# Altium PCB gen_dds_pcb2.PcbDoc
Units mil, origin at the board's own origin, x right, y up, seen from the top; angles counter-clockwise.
Board outline 6000 x 4000 mil, 2 copper layers (Top Layer, Bottom Layer); 89 components, 66 nets, 298 pads, 57 vias.
Unrouted connection lines stored in the file: 1.
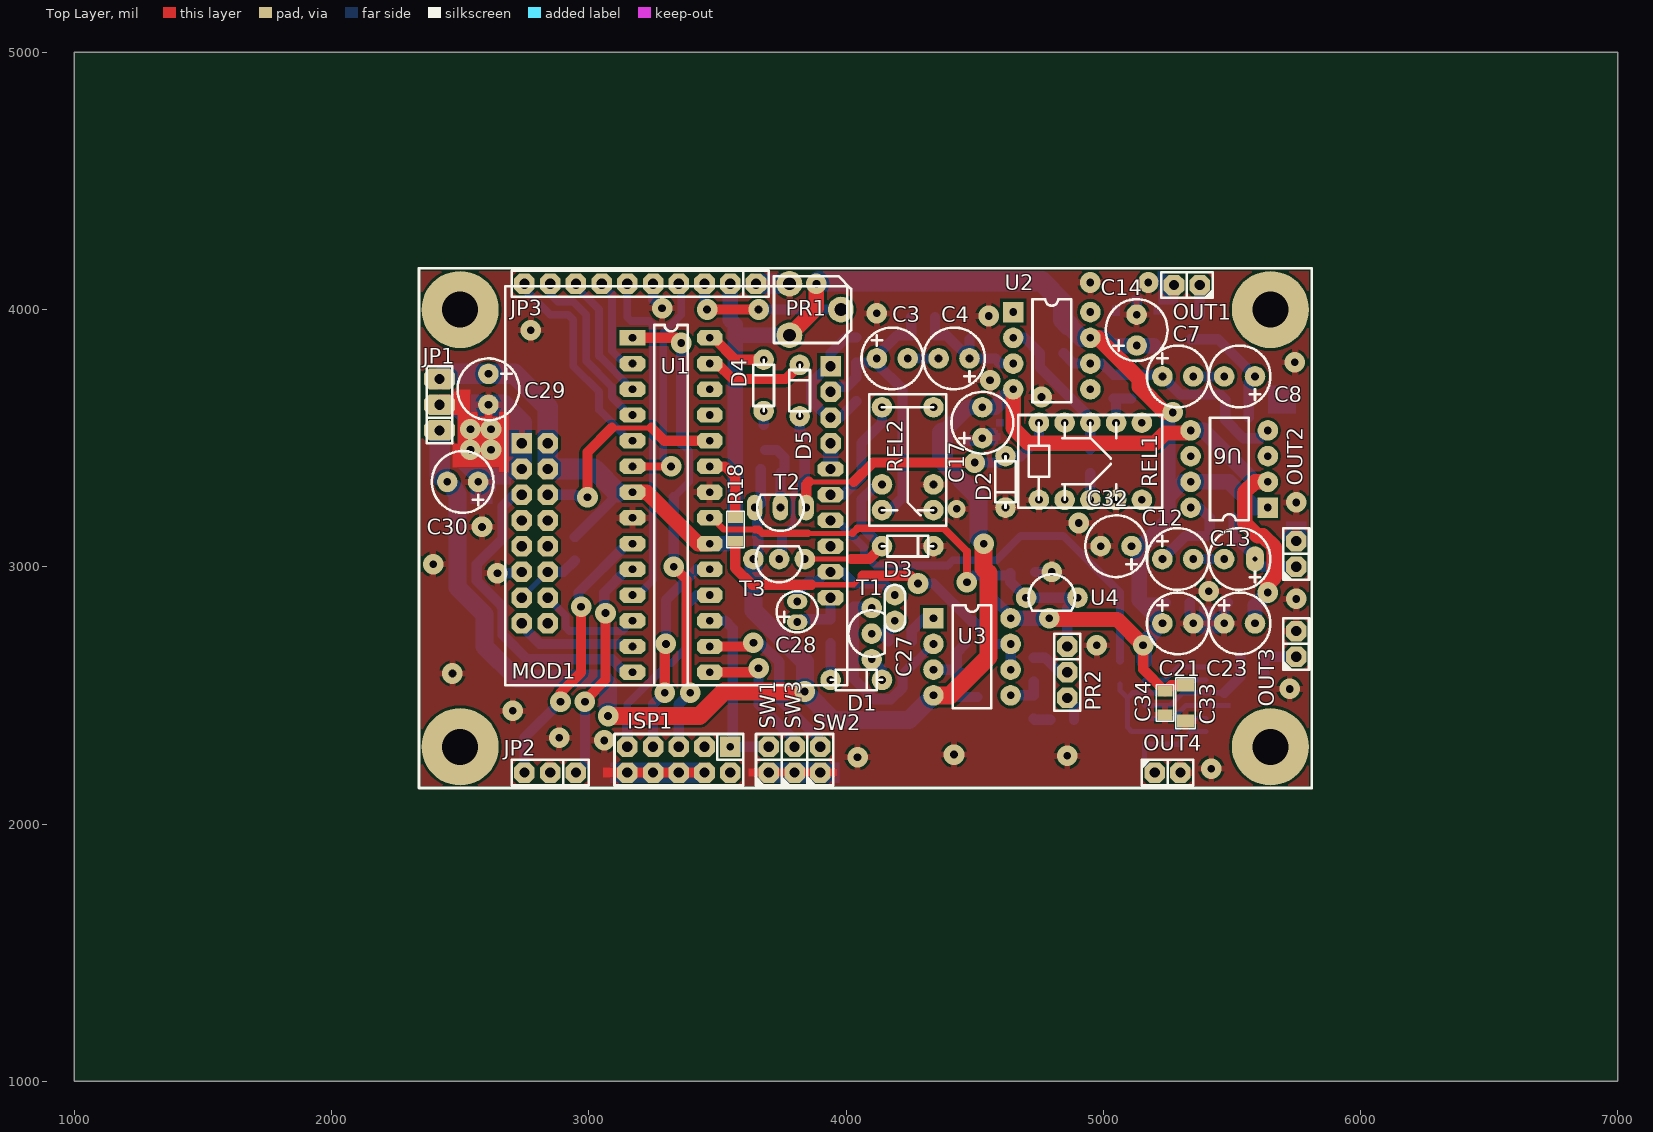
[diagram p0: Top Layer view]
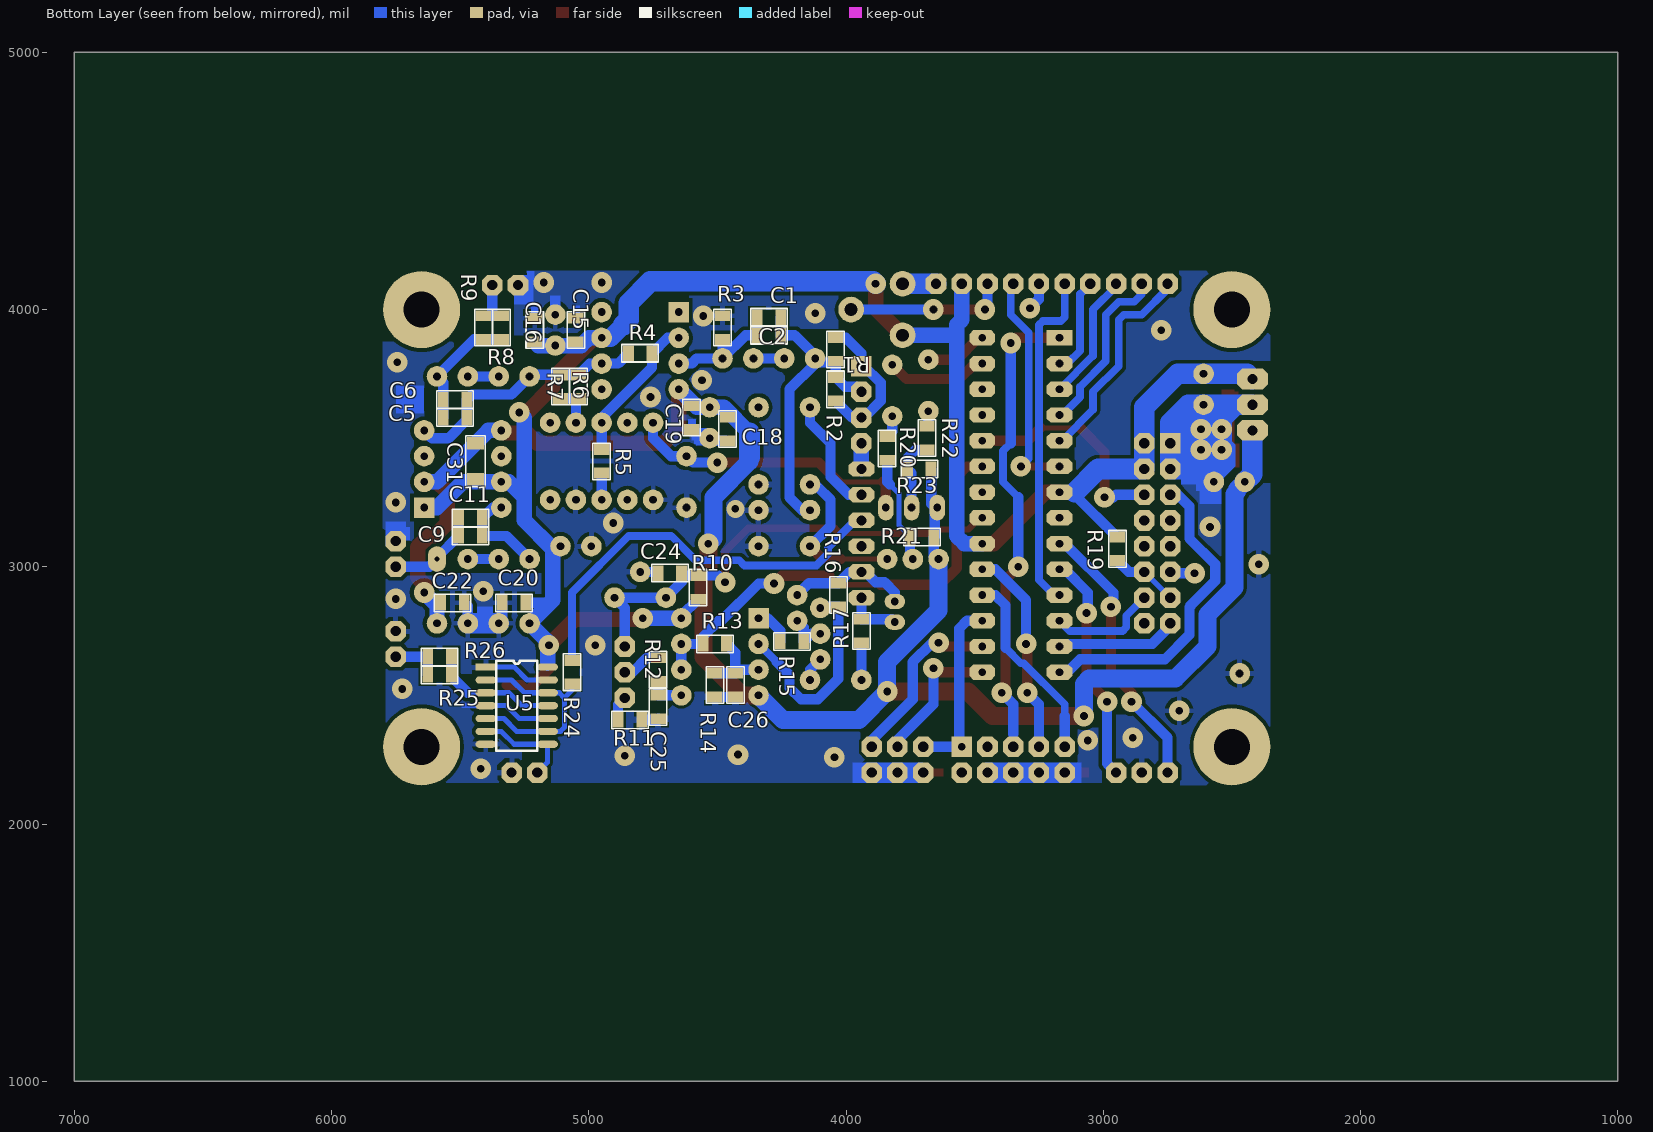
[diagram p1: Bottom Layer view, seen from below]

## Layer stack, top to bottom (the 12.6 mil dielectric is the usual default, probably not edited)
Top Layer: signal copper 1.4
Dielectric: dielectric 12.6, FR-4, Dk 4.8
Bottom Layer: signal copper 1.4

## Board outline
1000,1000 7000,1000 7000,5000 1000,5000

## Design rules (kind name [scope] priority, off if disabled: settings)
Clearance [All] p1: gap=11
PlaneConnect [All] p1: planeconnectstyle=Relief reliefexpansion=20 reliefentries=4 reliefconductorwidth=20 reliefairgap=10
PolygonConnect [All] p1: connectstyle=Relief reliefconductorwidth=25 reliefentries=4 polygonreliefangle="90 Angle"
RoutingVias [All] p1: holewidth=20 width=80 viastyle="Through Hole" minholewidth=20 minwidth=70 maxholewidth=20 maxwidth=80
SilkscreenOverComponentPads [All] p1: minsilkscreentomaskgap=10
SolderMaskExpansion [All] p1: expansion=4
Width [All] p1: maxlimit=120 minlimit=10 preferedwidth=10 minimp=50.000000 maximp=50.000000 favimp=50.000000
26 further rules are at their usual default settings.

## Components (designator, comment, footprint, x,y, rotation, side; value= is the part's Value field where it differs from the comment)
C1 "100n" 0805 4300,3970 r0 bottom
C2 "1n" 0805 4300,3900 r0 bottom
C3 "220u" CE6#1 4180,3810 r0 top
C4 "220u" CE6#1 4420,3810 r180 top
C5 "100n" 0805 5520,3580 r0 bottom
C6 "1n" 0805 5520,3650 r0 bottom
C7 "220u" CE6#1 5290,3740 r0 top
C8 "220u" CE6#1 5530,3740 r180 top
C9 "1n" 0805 5460,3120 r0 bottom
C11 "100n" 0805 5460,3190 r0 bottom
C12 "220u" CE6#1 5290,3030 r0 top
C13 "220u" CE6#2 5530,3030 r180 top
C14 "100u" CE6#1 5130,3920 r90 top
C15 "100n" 0805 5050,3920 r90 bottom
C16 "1n" 0805 5210,3920 r90 bottom
C17 "100u" CE6#1 4530,3560 r90 top
C18 "100n" 0805 4460,3535 r270 bottom
C19 "1n" 0805 4600,3580 r270 bottom
C20 "100n" 0805 5290,2860 r0 bottom
C21 "100u" CE6#1 5290,2780 r0 top
C22 "100n" 0805 5530,2860 r180 bottom
C23 "100u" CE6#1 5530,2780 r0 top
C24 "100n" 0805 4685,2975 r0 bottom
C25 "100n" 0805 4730,2455 r270 bottom
C26 "100n" 0805 4430,2540 r270 bottom
C27 "1u" C100 4190,2790 r90 top
C28 "10u" CE4 3810,2825 r90 top
C29 "220u" CE6#1 2610,3690 r270 top
C30 "220u" CE6#1 2510,3330 r180 top
C31 "1u" 1206 5440,3410 r90 bottom
C32 "100u" CE6#1 5050,3080 r180 top
C33 "1u" 1206 5320,2470 r270 top
C34 "1n" 0805 5240,2470 r270 top
D1 "BAT46" DO-35/200 3940,2560 r0 top
D2 "1N4148" DO-35/200 4620,3430 r270 top
D3 "1N4148" DO-35/200 4140,3080 r0 top
D4 "7V5" DO-35/200 3680,3605 r90 top
D5 "7V5" DO-35/200 3820,3585 r90 top
ISP1 "ISP" G2*5 3550,2300 r270 top
JP1 "ZASILANIE" G3#1 2420,3530 r180 top
JP2 "IMPULSATOR" G3#2 2950,2200 r270 top
JP3 "LCD2*16" G10 3650,4100 r270 top
MOD1 "DDS_MODUL" DDS_MODUL 2740,3480 r90 top
OUT1 "BNC" G2 5375,4095 r270 top
OUT2 "BNC" G2 5750,3000 r180 top
OUT3 "BNC" G2 5750,2650 r180 top
OUT4 "BNC" G2 5200,2200 r90 top
PR1 "10k" RM065 3880,4000 r180 top
PR2 "4,7k" G3#2 4860,2690 r0 top
R1 "100" 0805 4040,3845 r270 bottom
R2 "100" 0805 4040,3690 r270 bottom
R3 "4,7k" 0805 4480,3930 r270 bottom
R4 "510" 0805 4800,3830 r0 bottom
R5 "20" 0805 4950,3410 r90 bottom
R6 "470" 0805 5040,3700 r90 bottom
R7 "680" 0805 5110,3700 r90 bottom
R8 "100" 0805 5340,3930 r90 bottom
R9 "100" 0805 5410,3930 r90 bottom
R10 "1k" 0805 4575,2920 r270 bottom
R11 "100" 0805 4840,2405 r0 bottom
R12 "10k" 0805 4730,2600 r270 bottom
R13 "12k" 0805 4510,2700 r180 bottom
R14 "3k" 0805 4510,2540 r90 bottom
R15 "1k" 0805 4210,2710 r180 bottom
R16 "820" 0805 4030,2890 r270 bottom
R17 "100" 0805 3940,2750 r90 bottom
R18 "1k" 0805 3570,3145 r270 top
R19 "10k" 0805 2945,3070 r90 bottom
R20 "1k" 0805 3840,3460 r270 bottom
R21 "100k" 0805 3705,3115 r0 bottom
R22 "1k" 0805 3685,3500 r90 bottom
R23 "100k" 0805 3715,3380 r0 bottom
R24 "100" 0805 5065,2590 r270 bottom
R25 "100" 0805 5580,2580 r0 bottom
R26 "100" 0805 5580,2650 r0 bottom
REL1 "AZ850-5" AZ850 4950,3410 r90 top
REL2 "HFD23 005-1ZS" JRC23 4240,3620 r0 top
SW1 "SWITCH" G2 3700,2200 r180 top
SW2 "SWITCH" G2 3900,2200 r180 top
SW3 "SWITCH" G2 3800,2200 r180 top
T1 "BC547" TO92 4100,2640 r180 top
T2 "BC547" TO92A 3845,3230 r270 top
T3 "BC547" TO92 3840,3030 r270 top
U1 "ATMEGA8" DIP28A 3170,3890 r0 top
U2 "HFA1100" DIP8 4650,3990 r0 top
U3 "LM358" DIP8 4340,2800 r0 top
U4 "TL431" TO92B 4700,2880 r90 top
U5 "74ACT125" SOIC14 5280,2460 r180 bottom
U6 "HFA5002" DIP8 5640,3230 r180 top

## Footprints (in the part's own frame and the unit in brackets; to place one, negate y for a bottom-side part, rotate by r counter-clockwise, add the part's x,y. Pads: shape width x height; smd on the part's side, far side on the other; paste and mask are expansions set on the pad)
0805 [mil]
  rect 42x60 smd: 1(-46,0) 2(46,0)
  silkscreen extent -71,-34 71,34
1206 [mil]
  rect 50x67 smd: 1(-70,0) 2(70,0)
  silkscreen extent -99,-38 99,38
AZ850 [mil]
  round 80 hole 30: 0(-150,-200) 0(150,-200) 1(-150,0) 2(-150,100) 3(-150,-100) 4(150,0) 5(150,100) 6(150,-100) 7(-150,200) 8(150,200)
  silkscreen extent -180,-280 180,280
C100 [mil]
  round 80 hole 30: 1(0,0) 2(100,0)
  silkscreen extent -40,-40 140,40
CE4 [mil] "4mm, raster 2mm, pad 1,5mm*2mm"
  oval 60x80 hole 30: 1(-40,0) 2(40,0)
  silkscreen extent -80,-80 80,80
CE6#1 [mil] "6mm, raster 3mm, pad 2mm"
  round 80 hole 30: 1(-60,0) 2(60,0)
  silkscreen extent -120,-120 120,120
CE6#2 [mil] "6mm, raster 3mm, pad 2mm"
  oval 70x100 hole 20: 1(-60,0)
  round 80 hole 30: 2(60,0)
  silkscreen extent -120,-120 120,120
DDS_MODUL [mil]
  rect 80x80 hole 40: 1(0,0) 17(300,-1200)
  oct 80x80 hole 40: 2(0,-100) 3(-100,0) 4(-100,-100) 5(-200,0) 6(-200,-100) 7(-300,0) 8(-300,-100) 9(-400,0) 10(-400,-100) 11(-500,0) 12(-500,-100) 13(-600,0) 14(-600,-100) 15(-700,0) 16(-700,-100) 18(200,-1200) 19(100,-1200) 20(0,-1200)
  oct 60x100 hole 40: 21(-100,-1200) 22(-200,-1200) 23(-300,-1200) 24(-400,-1200) 25(-500,-1200) 26(-600,-1200)
  silkscreen extent -940,-1265 610,65
DIP8 [mil]
  rect 80x80 hole 30: 1(0,0)
  round 80 hole 30: 2(0,-100) 3(0,-200) 4(0,-300) 5(300,-300) 6(300,-200) 7(300,-100) 8(300,0)
  silkscreen extent 75,-350 225,50
DIP28A [mil]
  rect 100x60 hole 30: 1(0,0)
  oct 100x60 hole 30: 2(0,-100) 3(0,-200) 4(0,-300) 5(0,-400) 6(0,-500) 7(0,-600) 8(0,-700) 9(0,-800) 10(0,-900) 11(0,-1000) 12(0,-1100) 13(0,-1200) 14(0,-1300) 15(300,-1300) 16(300,-1200) 17(300,-1100) 18(300,-1000) 19(300,-900) 20(300,-800) 21(300,-700) 22(300,-600) 23(300,-500) 24(300,-400) 25(300,-300) 26(300,-200) 27(300,-100) 28(300,0)
  silkscreen extent 85,-1350 215,50
DO-35/200 [mil]
  round 80 hole 30: 1(0,0) 2(200,0)
  silkscreen extent 0,-40 200,40
G2 [mil]
  oct 80x80 hole 40: 1(0,0) 2(0,-100)
  silkscreen extent -50,-150 50,50
G2*5 [mil]
  rect 80x80 hole 30: 1(0,0)
  oct 80x80 hole 40: 2(100,0) 3(0,-100) 4(100,-100) 5(0,-200) 6(100,-200) 7(0,-300) 8(100,-300) 9(0,-400) 10(100,-400)
  silkscreen extent -50,-450 150,50
G3#1 [mil]
  oct 120x80 hole 40: 1(0,0) 2(0,-100) 3(0,-200)
  silkscreen extent -50,-250 50,50
G3#2 [mil]
  oct 80x80 hole 40: 1(0,0) 2(0,-100) 3(0,-200)
  silkscreen extent -50,-250 50,50
G10 [mil]
  oct 80x80 hole 40: 1(0,0) 2(0,-100) 3(0,-200) 4(0,-300) 5(0,-400) 6(0,-500) 7(0,-600) 8(0,-700) 9(0,-800) 10(0,-900)
  silkscreen extent -50,-950 50,50
JRC23 [mil]
  round 80 hole 30: 1(-100,0) 1(100,0) 2(100,-400) 3(-100,-400) 4(100,-300) 5(-100,-300)
  silkscreen extent -150,-460 150,50
RM065 [mil]
  round 100 hole 50: 1(100,100) 2(-100,0) 3(100,-100)
  silkscreen extent -140,-130 160,130
SOIC14 [mil]
  rect 80x28 smd: 1(-120,150)
  oval 80x28 smd: 2(-120,100) 3(-120,50) 4(-120,0) 5(-120,-50) 6(-120,-100) 7(-120,-150) 8(120,-150) 9(120,-100) 10(120,-50) 11(120,0) 12(120,50) 13(120,100) 14(120,150)
  silkscreen extent -80,-175 80,175
TO92 [mil]
  round 80 hole 30: 1(0,0) 2(0,-100) 3(0,-200)
  silkscreen extent -50,-191 91,-9
TO92A [mil]
  oval 100x60 hole 30: 1(0,0) 2(0,-100) 3(0,-200)
  silkscreen extent -50,-191 91,-9
TO92B [mil]
  round 80 hole 30: 1(0,0) 2(100,-100) 3(0,-200)
  silkscreen extent -50,-191 91,-9

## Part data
C1 C2 C5 C6 C9 C11 C15 C16 C18 C19 C20 C22 C24 C25 C26 C27 C31 C33 C34: library part C
C3 C4 C7 C8 C12 C13 C14 C17 C21 C23 C28 C29 C30 C32: library part CE
D1: library part DS
D2 D3: library part D
D4 D5: library part DZ
JP1 JP2: library part G3
JP3: library part G10
PR1 PR2: library part POT
R1 R2 R3 R4 R5 R6 R7 R8 R9 R10 R11 R12 R13 R14 R15 R16 R17 R18 R19 R20 R21 R22 R23 R24 R25 R26: library part R
REL1: library part RELAY2
REL2: library part RELAY
U1: library part ATMEGA8/DIP28
U3: library part NE5532

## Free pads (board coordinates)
  round 300 hole 140: 0(5650,4000) 1(5650,2300) 2(2500,4000) 3(2500,2300)

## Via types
v1: diameter 80, hole 30, Top Layer to Bottom Layer, 56 vias
v2: diameter 70, hole 30, Top Layer to Bottom Layer, 1 vias

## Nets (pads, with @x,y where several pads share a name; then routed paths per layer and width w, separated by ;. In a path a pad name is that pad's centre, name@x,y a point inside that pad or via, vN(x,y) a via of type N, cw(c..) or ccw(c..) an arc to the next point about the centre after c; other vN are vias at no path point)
+5V: C14.1 C15.1 C16.1 C20.1 C21.1 C29.1 C31.1 C32.1 C33.1 C34.1 JP1.3 JP3.2 MOD1.2 MOD1.4 PR1.1 R10.2 R19.2 U1.7 U1.20 U2.7 U3.8 U5.14 U6.1 U6.7 | length 7748.4
  Top Layer w40: v1(5155,2695) 5155,2601 C34.1 5264,2540 C33.1
  Top Layer w60: U1.7 3225,3290 3425,3090 U1.20 ; PR1.1 3885,4005 v1(3885,4100) ; v1(4790,2800) 4795,2795 5055,2795 v1(5155,2695) ; U2.7 4980,3890 5140,3730 5140,3700 5240,3600 v1(5270,3600)
  Bottom Layer w30: U5.14 5160,2630
  Bottom Layer w40: R19.2 2947.07,3116 3110,3278.93 3110,3290 ; R10.2 4640,2809 U3.8 ; 5140,2870 5150,2860 C20.1
  Bottom Layer w60: U1.20 3540,3090 3570,3120 3570,3900 ; JP3.2 3550,3960 3570,3940 3570,3900 ; PR1.1 3570,3900 ; U3.8 v1(4790,2800) ; U2.7 5000,3890 5030,3860 C14.1 C16.1@5196,3860 ; 5140,2870 5140,3070 5250,3180 5250,3270 ; 5150,2860 C21.1 5160,2710 5160,2630 ; v1(5270,3600) 5250,3580 5250,3270 ; U6.1 5590,3230 5490,3330 U6.7 5310,3330 5250,3270
  Bottom Layer w70: 4865,3940 4915,3890 U2.7
  Bottom Layer w80: JP1.3 2440,3750 C29.1 2710,3750 2840,3620 MOD1.2 MOD1.4 3020,3380 3110,3290 ; v1(3885,4100) 3895,4110 4760,4110 4845,4025 4845,3960 4865,3940
-5V: C17.2 C18.1 C19.1 C22.1 C23.2 C30.2 C31.2 JP1.1 R21.1 R23.1 T2.3 T3.3 U2.4 U3.4 U6.2 U6.5 | length 7468.1
  Top Layer w60: U2.4 4650,3540 4710,3480 5200,3480 5240,3520 5330,3520 U6.5 ; v1(5640,2900) 5640,2933.93 5665,2958.93 5665,3076.07 5621.07,3120 5600,3120 5550,3170 5550,3290 5590,3330 U6.2
  Top Layer w70: v1(3075,2420) 3430,2420 3525,2515 v1(3840,2515) ; U3.4 4405,2500 4554,2649 4554,2974.79 4535,2993.79 v1(4535,3090)
  Bottom Layer w40: T3.3@3650,3030 3659,3039 R21.1 3655,3119 3655,3230 3669,3244 R23.1
  Bottom Layer w60: 4375,3520 4475,3620 C17.2 4580,3620 U2.4 ; U6.5 5390,3530 C31.2 5590,3330 U6.2 ; C23.2 5590,2850 v1(5640,2900)
  Bottom Layer w70: C30.2 2480,3300 2480,3292.72 2490,3282.72 2490,2920 2595,2815 2595,2690 2720,2565 3055,2565 3075,2545 v1(3075,2420) ; T3.3 3640,2830 3840,2630 v1(3840,2515) 3950,2405 4245,2405 U3.4 ; 4375,3425 4375,3410 4515,3270 4515,3110 v1(4535,3090)
  Bottom Layer w80: JP1.1 2420,3360 C30.2 ; 4375,3425 4375,3520
GND: C14.2 C15.2 C16.2 C17.1 C18.2 C19.2 C20.2 C21.2 C22.2 C23.1 C24.2 C25.2 C26.2 C29.2 C30.1 C32.2 C33.2 C34.2 D2.2 D3.2 ISP1.4 ISP1.6 ISP1.8 ISP1.10 JP1.2 JP2.2 JP3.1 JP3.5 MOD1.1 MOD1.3 MOD1.11 OUT1.2 OUT2.2 OUT3.2 OUT4.2 PR1.3 R3.1 R11.1 R14.1 REL1.3 REL1.7 REL2.2 REL2.4 SW1.1 SW2.1 SW3.1 U1.8 U1.22 U4.2 U5.1 U5.4 U5.7 U5.10 U5.13 | length 2439.5
  Bottom Layer w20: C24.2 C24.2@4736,2975 ; U5.10 5270,2410 5320,2460 U5.4 5440,2460 ; U5.13 5240,2560 5290,2610 U5.1
  Bottom Layer w40: v1(2645,2975) 2735,2975 MOD1.11 ; JP3.5 3250,4040 v1(3285,4005) ; C26.2 R14.1 ; C17.1@4519,3489 C17.1 ; C25.2 4734,2405 R11.1 ; C24.2@4736,2980 U4.2 ; C20.2 5336,2794 C21.2 ; C23.1 5470,2846 C22.2
  Bottom Layer w80: JP1.2 C29.2 2670,3630 2740,3560 MOD1.1 MOD1.3 2620,3380 C30.1 ; ISP1.10 ISP1.8 ISP1.6 ISP1.4 ; JP3.1 PR1.3 ; C21.2 C23.1
  other v1: 5420,2215 4045,2260 4860,2265 4420,2270 3060,2325 2885,2335 2705,2440 5725,2525 2470,2585 4975,2695 5750,2875 5410,2905 2395,3010 2585,3155 4905,3170 5750,3250 2540,3455 2620,3455 2540,3535 2620,3535 4760,3660 4560,3725 5745,3795 2775,3920 4555,3975 4120,3985 4950,4105 5175,4105
  other v2: 4430,3225
NetC1_1: C1.1 C2.1 C3.1 MOD1.18 R1.2 R2.1 REL2.3 | length 1197.1
  Bottom Layer w40: MOD1.18 3960,3700 4004,3700 R2.1 4040,3794 4104,3794 C3.1 ; REL2.3 4170,3220 4220,3270 4220,3690 4120,3790 C3.1 ; C1.1 C2.1 4200,3900 4120,3820 C3.1
NetC1_2: C1.2 C2.2 C4.1 R3.2 U2.3 | length 493.6
  Bottom Layer w40: C1.2 C2.2 4390,3900 C4.1 ; R3.2 C4.1 ; U2.3 4600,3790 4580,3810 C4.1
NetC3_2: C3.2 C4.2 | length 120
  Bottom Layer w40: C3.2 C4.2
NetC5_1: C5.1 C6.1 C7.1 R4.2 R6.2 R7.2 U2.6 U6.4 | length 989.4
  Bottom Layer w40: R4.2 4886,3790 U2.6 4996,3790 R6.2 R7.2 5224,3746 C7.1 5300,3670 5454,3670 C6.1 C5.1 5474,3571 5545,3500 5609.59,3500 5639.59,3530 U6.4
NetC5_2: C5.2 C6.2 C8.1 R8.1 R9.1 | length 479.6
  Bottom Layer w40: R8.1 R9.1 5446,3884 C8.1 5566,3716 C6.2 C5.2
NetC7_2: C7.2 C8.2 | length 120
  Bottom Layer w40: C7.2 C8.2
NetC9_1: C9.1 C11.1 C12.1 U6.8 | length 381.8
  Bottom Layer w40: C12.1 5320,3120 C9.1 C11.1 5374,3230 U6.8
NetC9_2: C9.2 C11.2 C13.1 OUT2.1 | length 367.2
  Bottom Layer w40: C11.2 C9.2 5590,3036 C13.1 5620,3000 OUT2.1
NetC12_2: C12.2 C13.2 | length 120
  Bottom Layer w40: C12.2 C13.2
NetC25_1: C25.1 R12.2 U3.5 | length 143.4
  Bottom Layer w40: U3.5 4641,2501 C25.1 R12.2
NetC26_1: C26.1 R13.2 R14.2 U3.3 | length 303.9
  Bottom Layer w40: U3.3 4416,2600 C26.1 ; R13.2 4430,2666 C26.1 ; R14.2 C26.1
NetC27_1: C27.1 R15.2 T1.2 | length 167.2
  Bottom Layer w40: T1.2 4134,2740 R15.2 4164,2764 C27.1
NetC27_2: C27.2 C28.2 MOD1.25 R16.1 | length 485.4
  Bottom Layer w40: C28.2 3810,2900 3850,2940 3885,2940 3925,2980 MOD1.25 3986,2980 R16.1 4144,2936 C27.2
NetC28_1: C28.1 MOD1.26 R17.2 | length 218.6
  Bottom Layer w40: C28.1 3821,2796 R17.2 MOD1.26
NetD1_1: D1.1 R17.1 | length 144
  Bottom Layer w40: D1.1 R17.1
NetD1_2: D1.2 T1.1 | length 96.6
  Bottom Layer w40: T1.1 4140,2600 D1.2
NetD2_1: D2.1 REL1.8 T2.1 | length 1129.6
  Top Layer w20: 3855,3330 4030,3330
  Top Layer w40: T2.1 3845,3320 3855,3330 ; 4030,3330 4105,3405 v1(4500,3405)
  Bottom Layer w40: v1(4500,3405) 4595,3405 D2.1 4680,3430 4750,3500 REL1.8
NetD3_1: D3.1 REL2.5 T3.1 | length 638.7
  Top Layer w20: T3.1 4020,3030
  Top Layer w40: 4020,3030 4090,3030 D3.1
  Bottom Layer w40: D3.1 4060,3160 4060,3260 4110,3310 4130,3310 REL2.5
NetD4_1: D4.1 R22.2 | length 54
  Bottom Layer w40: R22.2@3680,3551 D4.1
NetD4_2: D4.2 U1.28 | length 245.2
  Top Layer w40: U1.28 3485,3890 3570,3805 D4.2
NetD5_1: D5.1 R20.1 | length 87.3
  Bottom Layer w40: D5.1 3820,3526 R20.1
NetD5_2: D5.2 U1.27 | length 397.6
  Top Layer w40: U1.27 3500,3790 3560,3730 3765,3730 D5.2
NetISP1_1: ISP1.1 SW1.2 U1.17 | length 716.6
  Bottom Layer w40: U1.17 3530,2790 3560,2760 3560,2310 ISP1.1 SW1.2
NetISP1_5: ISP1.5 U1.1 | length 1801.1
  Top Layer w40: U1.1 3340,3890 v1(3360,3870) ; v1(3330,3000) 3380,2950 3380,2525 v1(3395,2510)
  Bottom Layer w30: 3330,3270 3390,3330 3390,3450 3360,3480
  Bottom Layer w40: v1(3330,3000) 3330,3270 ; 3350,2350 3350,2465 v1(3395,2510) ; 3360,3480 v1(3360,3870)
NetISP1_7: ISP1.7 U1.19 | length 810.4
  Top Layer w40: v1(3295,2510) 3295,2695 v1(3300,2700)
  Bottom Layer w40: ISP1.7 3250,2465 v1(3295,2510) ; v1(3300,2700) 3300,2870 3420,2990 U1.19
NetISP1_9: ISP1.9 U1.18 | length 757.7
  Bottom Layer w30: 3150,2420 3150,2465 3310,2625 3320,2625 3380,2685
  Bottom Layer w40: ISP1.9 3150,2420 ; 3380,2685 3380,2850 3420,2890 U1.18
NetJP2_1: JP2.1 U1.10 | length 877.8
  Top Layer w40: v1@2990,2485 3065,2560 v1(3065,2820)
  Bottom Layer w40: JP2.1 2985,2235 v1(2985,2475) ; v1@3060,2825 3060,2900 3150,2990 U1.10
NetJP2_3: JP2.3 U1.9 | length 1044.8
  Top Layer w40: v1(2890,2475) 2890,2510 2970,2590 v1(2970,2845)
  Bottom Layer w40: JP2.3 2750,2335 v1(2890,2475) ; v1@2960,2880 2960,2900 3150,3090 U1.9
NetJP3_3: JP3.3 PR1.2 | length 624.1
  Top Layer w40: v1(3460,4000) v1(3660,4000)
  Bottom Layer w40: JP3.3 3450,4010 v1(3460,4000) ; v1(3660,4000) PR1.2
NetJP3_4: JP3.4 U1.6 | length 905.6
  Top Layer w30: U1.6 v1(3320,3390)
  Bottom Layer w30: v1(3320,3390) 3290,3420 3290,3910 3360,3980 3360,4090 JP3.4
NetJP3_6: JP3.6 U1.11 | length 1337.3
  Bottom Layer w30: JP3.6 3150,3970 3165,3955 3235,3955 3250,3940 3250,2950 3190,2890 U1.11
NetJP3_7: JP3.7 U1.2 | length 377.3
  Bottom Layer w30: JP3.7 3090,4060 3090,3840 3140,3790 U1.2
NetJP3_8: JP3.8 U1.3 | length 501.3
  Bottom Layer w30: JP3.8 2950,4090 3040,4000 3040,3819.64 3169.64,3690 U1.3
NetJP3_9: JP3.9 U1.4 | length 683.6
  Bottom Layer w30: JP3.9 2850,4060 2880,4030 2940,4030 2990,3980 2990,3800 3090,3700 3090,3660 3160,3590 U1.4
NetJP3_10: JP3.10 U1.5 | length 830.8
  Bottom Layer w30: JP3.10 2750,4080 2850,3980 2920,3980 2940,3960 2940,3780 3040,3680 3040,3610 3160,3490 U1.5
NetMOD1_5: MOD1.5 U1.14 | length 1241.5
  Bottom Layer w40: MOD1.5 2710,3280 2665,3235 2665,3110 2565,3010 2565,2945 2660,2850 2660,2848.99 2665,2843.99 2665,2735 2760,2640 3090,2640 3140,2590 U1.14
NetMOD1_6: MOD1.6 U1.24 | length 869.2
  Top Layer w20: 3090,3540 3244,3540
  Top Layer w40: v1(2995,3270) 2995,3445 3090,3540 ; 3244,3540 3294,3490 U1.24
  Bottom Layer w40: MOD1.6 2950,3280 2960,3270 v1(2995,3270)
NetMOD1_12: MOD1.12 MOD1.13 R19.1 | length 264.6
  Bottom Layer w20: MOD1.13 MOD1.12
  Bottom Layer w40: MOD1.12 2901,2980 R19.1
NetMOD1_14: MOD1.14 U1.12 | length 426.8
  Bottom Layer w30: MOD1.14 2910,2810 2910,2765 2925,2750 3130,2750 U1.12
NetMOD1_15: MOD1.15 U1.13 | length 473.1
  Bottom Layer w40: MOD1.15 2740,2770 2810,2700 3160,2700 U1.13
NetMOD1_17: MOD1.17 MOD1.19 R1.1 R2.2 | length 575.6
  Bottom Layer w40: R2.2 3976,3580 MOD1.19 3930,3580 3865,3645 3865,3715 3930,3780 MOD1.17 3940,3830 4001,3891 R1.1
NetMOD1_20: MOD1.20 MOD1.21 | length 100
  Bottom Layer w60: MOD1.21 MOD1.20
NetMOD1_22: MOD1.22 REL2.1 | length 452.1
  Bottom Layer w40: MOD1.22 3990,3280 4060,3350 4060,3480 4140,3560 REL2.1@4140,3620
NetMOD1_23: MOD1.23 R24.1 | length 1614.9
  Bottom Layer w30: MOD1.23 3965,3180 4070,3075 4070,3050 4115,3005 4395,3005 4415,3025 4585,3025 4680,3120 4845,3120 5065,2900 R24.1
NetOUT1_1: OUT1.1 R8.2 R9.2 | length 119
  Bottom Layer w40: 5375,3976 OUT1.1
NetOUT3_1: OUT3.1 R25.2 R26.2 | length 194
  Bottom Layer w40: R25.2 R26.2 OUT3.1
NetOUT4_1: OUT4.1 U5.6 U5.8 | length 387.3
  Bottom Layer w20: OUT4.1 5160,2240 U5.8 5290,2310 5340,2360 U5.6
NetPR2_2: PR2.2 R12.1 | length 153.2
  Bottom Layer w40: R12.1 4774,2646 4830,2590 PR2.2
NetPR2_3: PR2.3 R11.2 | length 95.8
  Bottom Layer w40: PR2.3 4886,2464 R11.2
NetR4_1: R4.1 R5.2 REL1.4 U2.2 | length 584
  Bottom Layer w40: U2.2 4694,3890 R4.1 4754,3776 4950,3580 REL1.4 R5.2
NetR5_1: R5.1 REL1.1 | length 104
  Bottom Layer w40: REL1.1 R5.1
NetR6_1: R6.1 R7.1 REL1.6 | length 168.1
  Bottom Layer w40: REL1.6 5050,3644 R6.1 R7.1
NetR13_1: R13.1 R18.2 U3.6 U3.7 | length 1442.2
  Top Layer w20: 3865,2930 4030,2930 4065,2965
  Top Layer w40: R18.2 3570,2995 3635,2930 3865,2930 ; 4065,2965 4250,2965 v1(4280,2935)
  Bottom Layer w40: v1(4280,2935) 4340,2935 4485,2790 4495,2790 4556,2729 R13.1 U3.7 U3.6
NetR15_1: R15.1 U3.1 | length 145.3
  Bottom Layer w40: R15.1 4256,2751 4305,2800 U3.1
NetR16_2: R16.2 T1.3 U3.2 | length 812.1
  Bottom Layer w30: 4270,2630 U3.2
  Bottom Layer w40: T1.3 4096,2844 R16.2 4030,2565 4110,2485 4175,2485 4220,2530 4220,2580 4270,2630
NetR18_1: R18.1 U1.23 | length 275.6
  Top Layer w40: U1.23 3530,3390 3570,3350 R18.1
NetR20_2: R20.2 R21.2 T3.2 | length 421.3
  Bottom Layer w20: R21.2 3751,3118 3794,3161 3794,3284 3830,3320
  Bottom Layer w40: T3.2@3750,3030 3751,3031 R21.2 ; 3830,3320 3840,3330 R20.2
NetR22_1: R22.1 R23.2 T2.2 | length 289.1
  Bottom Layer w40: R22.1 3731,3454 3761,3424 R23.2 3745,3364 T2.2
NetR24_2: R24.2 U5.2 U5.5 U5.9 U5.12 | length 847.3
  Bottom Layer w20: R24.2 5065,2520 5095,2490 ; U5.5 5330,2410 5280,2360 U5.9 5110,2360 5095,2375 5095,2490 ; U5.2 5300,2560 5250,2510 U5.12 5115,2510 5095,2490
NetR25_1: R25.1 R26.1 U5.3 U5.11 | length 497.2
  Bottom Layer w20: U5.11 5260,2460 5310,2510 U5.3 5470,2510
  Bottom Layer w40: 5470,2510 5534,2574 R25.1 R26.1
NetSW2_2: SW2.2 U1.16 | length 707.3
  Top Layer w40: U1.16 v1@3650,2690
  Bottom Layer w40: v1(3640,2705) 3665,2705 3740,2630 3740,2485 3900,2325 SW2.2
NetSW3_2: SW3.2 U1.15 | length 548
  Top Layer w40: U1.15 v1@3655,2590
  Bottom Layer w40: v1(3660,2605) 3660,2465 3800,2325 SW3.2
REF: C24.1 PR2.1 R10.1 U1.21 U4.1 U4.3 | length 1900.7
  Top Layer w20: 3850,3130 4025,3130
  Top Layer w25: U1.21 3480,3190 3525,3145 3645,3145
  Top Layer w30: 3645,3145 3660,3145 3675,3130 3850,3130 ; 4025,3130 4045,3150 4380,3150 4470,3060 v1(4470,2940)
  Bottom Layer w40: v1(4470,2940) 4496,2966 R10.1 4630,2966 C24.1 4639,2941 U4.1 U4.3 4860,2840 PR2.1
pads on no net: ISP1.2 ISP1.3 MOD1.7 MOD1.8 MOD1.9 MOD1.10 MOD1.16 MOD1.24 REL1.0 REL1.2 REL1.5 U1.25 U1.26 U2.1 U2.5 U2.8 U6.3 U6.6
copper on no net: | length 15
  Bottom Layer w40: 2645,2975 2660,2975

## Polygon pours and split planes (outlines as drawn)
GND on Bottom Layer "Top Layer-No Net" (solid, pour order 22): 3900,2160 3900,2240 3910,2240 3945,2275 3945,2365 4250,2365 4255,2370 4400,2515 4550,2515 4620,2515 4700,2435 4705,2440 4910,2440 4910,2880 4917.47,2887.47 5034.74,2887.47 5034.74,2525.26 5035,2525 5085,2475 5085,2370 5090,2365 5145,2310 5145,2175 5145,2160 3900,2160
GND on Bottom Layer "Top Layer-No Net" (solid, pour order 17): 2350,3800 2725,3800 2890,3635 2890,3430 3035,3430 3090,3375 3110,3375 3110,3515 3025,3600 3025,3675 2925,3775 2925,3960 2920,3965 2840,3965 2835,3965 2745,4055 2740,4060 2720,4060 2720,4065 2705,4080 2705,4150 2600,4150 2350,3900 2350,3895 2350,3800
GND on Bottom Layer "Top Layer-No Net" (solid, pour order 18): 2805,2190 2765,2230 2765,2315 2765,2320 2875,2430 2880,2425 2960,2425 2960,2230 2920,2230 2905,2230 2890,2215 2890,2190 2805,2190
GND on Bottom Layer "Top Layer-No Net" (solid, pour order 19): 3150,2160 3005,2160 3005,2375 3100,2375 3100,2240 3150,2240 3150,2160
GND on Bottom Layer "Top Layer-No Net" (solid, pour order 20): 4810,3090 4855,3090 5040,2905 5034.74,2899.74 5034.74,2852.26 4882.74,2852.26 4850,2885 4810,2925 4810,3090
GND on Bottom Layer "Top Layer-No Net" (solid, remove dead copper, pour order 21): 5190,2560 5190,2700 5190,2860 5175,2875 5175,2975 5790,2975 5790,2725 5775,2710 5745,2680 5645,2680 5520,2680 5515,2675 5510,2670 5510,2600 5495,2585 5265,2585 5250,2585 5225,2560 5190,2560
GND on Bottom Layer "Top Layer-No Net" (solid, pour order 23): 5260,2160 5260,2280 5405,2425 5405,2475 5475,2475 5545,2545 5550,2550 5650,2550 5650,2595 5660,2605 5790,2605 5790,2375 5575,2160 5260,2160
GND on Bottom Layer "Top Layer-No Net" (solid, pour order 24): 5220,3525 4775,3525 4680,3430 4635,3385 4340,3385 4340,3105 4345,3100 4410,3035 4515,3035 4575,3035 4675,3135 4850,3135 5065,2920 5110,2920 5110,3085 5220,3195 5220,3525
GND on Bottom Layer "Top Layer-No Net" (solid, pour order 25): 4415,3425 4415,3515 4505,3605 4630,3605 4630,3630 4660,3660 4675,3675 4675,3750 4750,3750 4875,3625 4875,3610 4870,3605 4735,3605 4735,3600 4705,3570 4730,3545 4730,3520 4730,3505 4650,3425 4415,3425
GND on Bottom Layer "Top Layer-No Net" (solid, pour order 26): 4477.26,3053.04 4417.26,3053.04 4387.26,3023.04 4372.26,3038.04 4142.26,3038.04 4142.26,3163.04 4232.26,3253.04 4237.26,3258.04 4237.26,3698.04 4237.26,3743.04 4277.26,3783.04 4287.26,3773.04 4567.26,3773.04 4572.26,3773.04 4612.26,3733.04 4612.26,3678.04 4592.26,3678.04 4567.26,3653.04 4557.26,3643.04 4467.26,3643.04 4457.26,3643.04 4332.26,3518.04 4332.26,3398.04 4477.26,3253.04 4483.94,3246.36 4483.94,3053.3
GND on Bottom Layer "Top Layer-No Net" (solid, pour order 27): 4610,3825 4610,4070 4030,4070 4030,3925 4020,3915 4030,3925 4225,3925 4225,3995 4230,4000 4370,4000 4370,3945 4375,3940 4490,3825 4610,3825
GND on Bottom Layer "Top Layer-No Net" (solid, pour order 28): 5710,3080 5680,3110 5680,3185 5680,3540 5640,3580 5640,3720 5590,3770 5525,3835 5525,3870 5530,3875 5800,3875 5800,3150 5790,3140 5790,3080 5710,3080
GND on Bottom Layer "Top Layer-No Net" (solid, pour order 29): 5315,4115 5315,4075 5290,4050 5290,3950 5290,3900 4950,3900 4850,4000 4800,4050 4800,4150 5250,4150 5285,4115 5315,4115
GND on Bottom Layer "Top Layer-No Net" (solid, pour order 30): 2540,3035 2565,3035 2645,3115 2645,3245 2650,3245 2725,3320 2725,3380 2540,3380 2525,3365 2525,3035 2540,3035
GND on Bottom Layer "Top Layer-No Net" (solid, pour order 31): 2350,3325 2350,2375 2375,2375 2600,2150 2700,2150 2700,2220 2730,2250 2730,2345 2845,2460 2850,2465 2850,2525 2730,2525 2570,2685 2575,2690 2575,2805 2575,2820 2475,2920 2465,2930 2465,3280 2420,3325 2350,3325
GND on Top Layer "Top Layer-No Net" (solid, pour order 32): 2349.2,2149.2 2349.2,4149.2 5799.2,4149.2 5799.2,2149.2 2349.2,2149.2

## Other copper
Top Layer:
  rectangle net GND: 2595,3575 2625,3610
  rectangle net GND: 2420,3590 2505,3670
  rectangle net GND: 2490,3400 2670,3585
  rectangle net GND: 2651.8,3366.37 2689,3600.7
  rectangle net GND: 2470,3385 2660,3410
  rectangle net GND: 2470,3400 2505,3480
  rectangle net GND: 2490,3570 2540,3690
  rectangle net GND: 2474.25,3590 2505,3681.22
  rectangle net GND: 2552.5,3575 2570,3596.22
  rectangle net GND: 2540,3570 2568.2,3600.7
  rectangle net GND: 3055,2180 3490,2220
  rectangle net GND: 3620,2185 3965,2215
Bottom Layer:
  rectangle net GND: 3700,2160 3975,2240
  rectangle net GND: 2500,3475 2715,3595
  rectangle net GND: 2500,3410 2715,3490
  region net GND: 2506.97,3551.97 2560,3605 2510.5,3654.5 2457.47,3601.46
  rectangle net GND: 2485,3390 2515,3475
  region net GND: 2548.64,3326.36 2587.53,3365.25 2523.89,3428.89 2485,3390
  rectangle net GND: 2530,3370 2625,3430
  region net GND: 2523.89,3436.11 2559.25,3471.46 2520.36,3510.36 2485,3475
  rectangle net GND: 3085,2160 3150,2240
  rectangle net GND: 5372,2790 5435,2846
  rectangle net GND: 5415,2450 5495,2470
  rectangle net GND: 4460,3470 4535,3510
  rectangle net GND: 4530,3470.62 4582.59,3540
  rectangle net GND: 4575,3490 4600,3520
  rectangle net GND: 4580.44,3478.04 4590,3532.26
  rectangle net GND: 5710,3080 5790,3175
  rectangle net GND: 5695,3101.53 5745,3155
  rectangle net GND: 5110,4000 5150,4055
  rectangle net GND: 5215,4019.23 5290,4135
  rectangle net GND: 5210,4105 5240.97,4150
  rectangle net GND: 5035,3975 5065,4015
  rectangle net GND: 5195,3980 5225,4010
  rectangle net GND: 4582.91,3545 4615,3574.36
  rectangle net GND: 2540.43,3244.14 2625,3370
  rectangle net GND: 2587.53,3319.91 2697.41,3365.25
  rectangle net GND: 2595,3295 2640,3355
  rectangle net GND: 5640,3595 5750,3705

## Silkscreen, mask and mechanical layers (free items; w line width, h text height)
Top Overlay:
  lines w10: 2340,2140 2340,4160 5810,4160 5810,2140 2340,2140
Mechanical 1:
  lines w10: 2325,2125 2325,4175 5825,4175 5825,2125 2325,2125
